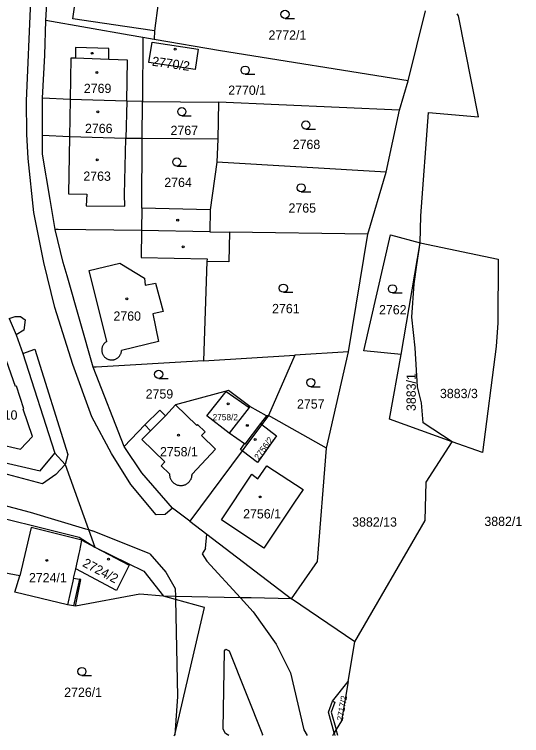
# Model space of a CAD drawing. Extents: x -527335 to -526256, y -1079142 to -1077809.
# Drawn here: x -526999.4 to -526906.2, y -1079141.5 to -1079009.2 of the extents above; entities that cross this region are included whole.
import ezdxf

# ---------------------------------------------------------------- set-up
doc = ezdxf.new("R2010")
doc.units = 0
for name, color, linetype in [('Vrstva 1', 7, 'Continuous'), ('Vrstva 2', 7, 'Continuous'), ('Vrstva 3', 7, 'Continuous'), ('Vrstva 4', 7, 'Continuous'), ('Vrstva 5', 7, 'Continuous')]:
    doc.layers.add(name, color=color, linetype=linetype)

msp = doc.modelspace()

# ---------------------------------------------------------------- linework, layer by layer
at = {"layer": 'Vrstva 1'}
for p, q in [((-526993.58, -1079010.29), (-526992.59, -1078994.21)), ((-526926.99, -1079021.34), (-526923.82, -1079008.49)), ((-526975.76, -1079013.38), (-526975.83, -1079025.14)), ((-526973.68, -1079013.74), (-526975.76, -1079013.38)), ((-526961.48, -1079015.86), (-526973.68, -1079013.74)), ((-526926.99, -1079021.34), (-526961.48, -1079015.86)), ((-526928.59, -1079026.75), (-526926.99, -1079021.34)), ((-526994.18, -1079031.41), (-526994.21, -1079024.51)), ((-526975.87, -1079031.93), (-526975.83, -1079025.14)), ((-526975.83, -1079025.14), (-526961.85, -1079025.27)), ((-526961.85, -1079025.27), (-526961.95, -1079032.04)), ((-526928.59, -1079026.75), (-526961.85, -1079025.27)), ((-526931.03, -1079038.09), (-526928.59, -1079026.75)), ((-526961.95, -1079032.04), (-526975.87, -1079031.93)), ((-526961.95, -1079032.04), (-526962.14, -1079036.28)), ((-526962.14, -1079036.28), (-526963.38, -1079045.02)), ((-526931.03, -1079038.09), (-526962.14, -1079036.28)), ((-526934.42, -1079049.52), (-526931.03, -1079038.09)), ((-526963.38, -1079045.02), (-526963.42, -1079049.05)), ((-526963.42, -1079049.05), (-526959.83, -1079049.11)), ((-526934.42, -1079049.52), (-526959.83, -1079049.11)), ((-526937.98, -1079071.07), (-526934.42, -1079049.52)), ((-526928.28, -1079071.58), (-526924.77, -1079051.08)), ((-526964.58, -1079072.72), (-526947.84, -1079071.72)), ((-526947.84, -1079071.72), (-526952.64, -1079082.8)), ((-526937.98, -1079071.07), (-526947.84, -1079071.72)), ((-526942, -1079088.79), (-526937.98, -1079071.07)), ((-526979.19, -1079088.45), (-526984.86, -1079073.9)), ((-526953.05, -1079082.84), (-526956.09, -1079081.1)), ((-526952.64, -1079082.8), (-526953.87, -1079084.41)), ((-526952.64, -1079082.8), (-526953.05, -1079082.84)), ((-526942, -1079088.79), (-526952.64, -1079082.8)), ((-526957.52, -1079089.25), (-526967.13, -1079102.16)), ((-526943.64, -1079109.56), (-526942, -1079088.79)), ((-526948.41, -1079116.44), (-526943.64, -1079109.56)), ((-526936.82, -1079124.34), (-526948.41, -1079116.44)), ((-526938.05, -1079131.59), (-526936.82, -1079124.34))]:
    msp.add_line(p, q, dxfattribs=at)
for points in [[(-526972.18, -1078997.1), (-526972.98, -1079000.63), (-526972.95, -1079007.03), (-526973.6, -1079012.17), (-526973.68, -1079013.74)], [(-526924.77, -1079051.08), (-526924.66, -1079046.13), (-526923.27, -1079027.14), (-526914.08, -1079027.98), (-526917.74, -1079009.39), (-526917.97, -1079009.06)], [(-526994.21, -1079024.51), (-526993.76, -1079016.63), (-526993.58, -1079010.29)], [(-526975.76, -1079013.38), (-526978.26, -1079012.95), (-526993.58, -1079010.29)], [(-526974.63, -1079018), (-526974.06, -1079014.26), (-526965.59, -1079015.55), (-526966.15, -1079019.3), (-526974.63, -1079018)], [(-526975.83, -1079025.14), (-526978.72, -1079025.11), (-526989.12, -1079024.77), (-526994.21, -1079024.51)], [(-526991.83, -1079048.67), (-526992.77, -1079043.16), (-526994.21, -1079034.79), (-526994.18, -1079031.41)], [(-526975.87, -1079031.93), (-526978.87, -1079031.91), (-526989.23, -1079031.65), (-526994.18, -1079031.41)], [(-526963.38, -1079045.02), (-526975.94, -1079044.75), (-526975.87, -1079031.93)], [(-526963.42, -1079049.05), (-526976, -1079048.8), (-526991.33, -1079048.67), (-526991.83, -1079048.67)], [(-526984.86, -1079073.9), (-526989.68, -1079057.15), (-526990.38, -1079054.69), (-526991.83, -1079048.67)], [(-526959.83, -1079049.11), (-526959.97, -1079054.59), (-526963.97, -1079054.51), (-526964.58, -1079072.72)], [(-526928.28, -1079071.58), (-526935.16, -1079070.89), (-526930.27, -1079049.59), (-526924.77, -1079051.08)], [(-526918.92, -1079087.59), (-526924.25, -1079084.15), (-526924.53, -1079080.46), (-526925.29, -1079077.55), (-526925.71, -1079070.34), (-526926.3, -1079064.74), (-526925.9, -1079058.59), (-526925.39, -1079055.11), (-526924.77, -1079051.08)], [(-526924.77, -1079051.08), (-526910.45, -1079054.06), (-526910.54, -1079065.78), (-526910.82, -1079070.11), (-526913.35, -1079089.58), (-526918.92, -1079087.59)], [(-527000.3, -1079064.95), (-526999.03, -1079067.99), (-526997.79, -1079071.43), (-526991.96, -1079089.49), (-526991.9, -1079089.68)], [(-526918.92, -1079087.59), (-526930.42, -1079083.47), (-526928.28, -1079071.58)], [(-526964.58, -1079072.72), (-526984.32, -1079073.9), (-526984.86, -1079073.9)], [(-526956.09, -1079081.1), (-526960.02, -1079078.17), (-526969.73, -1079080.81), (-526971.59, -1079082.86), (-526972.64, -1079081.8), (-526975.39, -1079084.5), (-526979.19, -1079088.45)], [(-526953.05, -1079082.84), (-526954.11, -1079084.23), (-526957, -1079088.03), (-526957.07, -1079087.98), (-526959.89, -1079086.05), (-526963.98, -1079082.86), (-526960.43, -1079078.38), (-526956.23, -1079081.29), (-526956.09, -1079081.1)], [(-526953.87, -1079084.41), (-526956.71, -1079088.16), (-526957.52, -1079089.25)], [(-526953.87, -1079084.41), (-526951.17, -1079086.54), (-526954.69, -1079091.43), (-526957.52, -1079089.25)], [(-526936.82, -1079124.34), (-526923.9, -1079102.05), (-526923.68, -1079095.01), (-526918.92, -1079087.59)], [(-526967.13, -1079102.16), (-526970.32, -1079099.79), (-526975.94, -1079093.33), (-526979.19, -1079088.45)], [(-527006.59, -1079090.18), (-526994.63, -1079092.92), (-526991.9, -1079089.68)], [(-526991.9, -1079089.68), (-526990.02, -1079091.79), (-526985.75, -1079103.72), (-526984.58, -1079106.98)], [(-527008.36, -1079099.95), (-526996.25, -1079102.89), (-526987.44, -1079105.14), (-526984.58, -1079106.98)], [(-526967.13, -1079102.16), (-526963.98, -1079104.57), (-526948.41, -1079116.44)], [(-526984.58, -1079106.98), (-526978.28, -1079110.24), (-526980.57, -1079114.9), (-526988.08, -1079110.95), (-526987.42, -1079108.12), (-526987.3, -1079107.62), (-526986.99, -1079105.64), (-526984.58, -1079106.98)], [(-526984.58, -1079106.98), (-526975.58, -1079111.34), (-526971.93, -1079115.94)], [(-526971.93, -1079115.94), (-526976.33, -1079115.57), (-526988.12, -1079117.78), (-526988.51, -1079117.72), (-526989.62, -1079117.54), (-526999.27, -1079115.18), (-526998.37, -1079112.24), (-527009.82, -1079110.06)], [(-526969.89, -1079141.41), (-526964.4, -1079118), (-526969.76, -1079116.53), (-526971.93, -1079115.94)], [(-526948.41, -1079116.44), (-526955.84, -1079116.28), (-526957.82, -1079116.24), (-526969.77, -1079115.99), (-526971.93, -1079115.94)], [(-526940.61, -1079141.01), (-526941.63, -1079137.22), (-526940.92, -1079135.23), (-526938.05, -1079131.59)], [(-526938.05, -1079131.59), (-526939.27, -1079138.83), (-526940.25, -1079140.42), (-526940.61, -1079141.01)], [(-526940.86, -1079141.53), (-526940.61, -1079141.01)], [(-526970.05, -1079141.53), (-526969.89, -1079141.41)]]:
    msp.add_lwpolyline(points, dxfattribs=at)
at = {"layer": 'Vrstva 3'}
for p, q in [((-526949.62, -1079009.9), (-526947.87, -1079009.9)), ((-526956.95, -1079020.15), (-526955.2, -1079020.15)), ((-526968.59, -1079027.75), (-526966.84, -1079027.75)), ((-526945.8, -1079030.21), (-526944.05, -1079030.21)), ((-526969.5, -1079037), (-526967.75, -1079037)), ((-526946.65, -1079041.73), (-526944.9, -1079041.73)), ((-526949.92, -1079060.16), (-526948.17, -1079060.16)), ((-526929.87, -1079060.28), (-526928.12, -1079060.28)), ((-526972.83, -1079075.98), (-526971.08, -1079075.98)), ((-526944.89, -1079077.49), (-526943.14, -1079077.49)), ((-526986.95, -1079130.53), (-526985.2, -1079130.53))]:
    msp.add_line(p, q, dxfattribs=at)
for centre in [(-526949.62, -1079009.15), (-526956.95, -1079019.4), (-526968.59, -1079027), (-526945.8, -1079029.46), (-526969.5, -1079036.25), (-526946.65, -1079040.98), (-526949.92, -1079059.41), (-526929.87, -1079059.53), (-526972.83, -1079075.23), (-526944.89, -1079076.74), (-526986.95, -1079129.78)]:
    msp.add_circle(centre, 0.75, dxfattribs=at)
at = {"layer": 'Vrstva 4'}
for p, q in [((-526988.63, -1079009.95), (-526987.21, -1078999.98)), ((-526997.1, -1079025), (-526996.31, -1079006.69)), ((-526979.03, -1079011.37), (-526988.63, -1079009.95)), ((-526973.6, -1079012.17), (-526979.03, -1079011.37)), ((-526988.11, -1079015.21), (-526988.12, -1079017.21)), ((-526982.01, -1079015.44), (-526988.11, -1079015.21)), ((-526982.02, -1079017.44), (-526982.01, -1079015.44)), ((-526988.99, -1079017.18), (-526989.12, -1079024.77)), ((-526988.12, -1079017.21), (-526988.99, -1079017.18)), ((-526982.02, -1079017.44), (-526988.12, -1079017.21)), ((-526978.56, -1079017.57), (-526982.02, -1079017.44)), ((-526978.72, -1079025.11), (-526978.56, -1079017.57)), ((-526997.09, -1079031.14), (-526997.1, -1079025)), ((-526989.12, -1079024.77), (-526989.23, -1079031.65)), ((-526978.72, -1079025.11), (-526978.87, -1079031.91)), ((-526996.85, -1079035.58), (-526997.09, -1079031.14)), ((-526989.23, -1079031.65), (-526989.41, -1079042.08)), ((-526979.09, -1079042.22), (-526978.87, -1079031.91)), ((-526995.75, -1079045.53), (-526996.85, -1079035.58)), ((-526989.41, -1079042.08), (-526986.04, -1079042.13)), ((-526986.04, -1079042.13), (-526986.18, -1079044.27)), ((-526979.05, -1079044.35), (-526979.09, -1079042.22)), ((-526986.18, -1079044.27), (-526979.05, -1079044.35)), ((-526993.94, -1079054.67), (-526995.75, -1079045.53)), ((-526975.94, -1079044.75), (-526976, -1079048.8)), ((-526976, -1079048.8), (-526976.07, -1079053.8)), ((-526991.93, -1079062.93), (-526993.94, -1079054.67)), ((-526985.61, -1079056.17), (-526979.98, -1079054.79)), ((-526979.98, -1079054.79), (-526975.45, -1079057.6)), ((-526976.07, -1079053.8), (-526963.96, -1079054.01)), ((-526963.96, -1079054.01), (-526963.97, -1079054.51)), ((-526982.38, -1079069.18), (-526985.61, -1079056.17)), ((-526975.45, -1079057.6), (-526975.34, -1079058.88)), ((-526975.34, -1079058.88), (-526973.41, -1079058.52)), ((-526973.41, -1079058.52), (-526972.01, -1079063.72)), ((-526988.62, -1079073.43), (-526991.93, -1079062.93)), ((-526972.01, -1079063.72), (-526973.93, -1079064.11)), ((-526973.93, -1079064.11), (-526972.86, -1079069.19)), ((-527000.3, -1079064.95), (-526999.18, -1079064.63)), ((-526999.18, -1079064.63), (-526998.24, -1079064.6)), ((-526998.24, -1079064.6), (-526997.4, -1079065.25)), ((-526997.4, -1079065.25), (-526997.64, -1079067.14)), ((-526997.64, -1079067.14), (-526999.03, -1079067.99)), ((-526972.86, -1079069.19), (-526979.66, -1079070.86)), ((-526997.79, -1079071.43), (-526995.59, -1079070.62)), ((-526995.59, -1079070.62), (-526989.55, -1079089.95)), ((-526999.16, -1079077.44), (-527000.78, -1079072.77)), ((-526985.11, -1079083.05), (-526988.62, -1079073.43)), ((-526998.99, -1079077.38), (-526999.16, -1079077.44)), ((-526997.6, -1079081.58), (-526998.99, -1079077.38)), ((-526965.85, -1079084.59), (-526969.73, -1079080.81)), ((-526956.23, -1079081.29), (-526959.89, -1079086.05)), ((-526997.76, -1079081.63), (-526997.6, -1079081.58)), ((-526996.01, -1079086.61), (-526997.76, -1079081.63)), ((-526981.48, -1079089.76), (-526985.11, -1079083.05)), ((-526971.59, -1079082.86), (-526974.33, -1079085.57)), ((-526974.33, -1079085.57), (-526975.39, -1079084.5)), ((-526965.7, -1079084.43), (-526965.85, -1079084.59)), ((-526964.32, -1079085.78), (-526965.7, -1079084.43)), ((-526954.11, -1079084.23), (-526953.87, -1079084.41)), ((-526998.21, -1079088.98), (-526996.01, -1079086.61)), ((-526974.33, -1079085.57), (-526975.94, -1079087.16)), ((-526964.95, -1079086.43), (-526964.32, -1079085.78)), ((-526962.37, -1079088.96), (-526964.95, -1079086.43)), ((-527005.52, -1079087.25), (-526998.21, -1079088.98)), ((-526975.94, -1079087.16), (-526971.7, -1079091.28)), ((-526957.8, -1079089.04), (-526957.07, -1079087.98)), ((-526966.71, -1079093.57), (-526962.37, -1079088.96)), ((-526957.52, -1079089.25), (-526957.8, -1079089.04)), ((-526989.55, -1079089.95), (-526990.02, -1079091.79)), ((-526977.96, -1079095.46), (-526981.48, -1079089.76)), ((-526994.16, -1079095.3), (-527010.79, -1079090.93)), ((-526990.02, -1079091.79), (-526991.73, -1079093.6)), ((-526971.7, -1079091.28), (-526972.4, -1079092)), ((-526972.4, -1079092), (-526970.84, -1079093.51)), ((-526954.61, -1079094.38), (-526952.95, -1079092.04)), ((-526952.95, -1079092.04), (-526946.32, -1079096.34)), ((-526991.73, -1079093.6), (-526994.16, -1079095.3)), ((-526961.27, -1079101.93), (-526955.72, -1079093.58)), ((-526955.72, -1079093.58), (-526954.61, -1079094.38)), ((-526973.28, -1079101.02), (-526977.96, -1079095.46)), ((-526946.32, -1079096.34), (-526947.9, -1079098.7)), ((-527007.27, -1079097.63), (-526996.46, -1079100.53)), ((-526970.32, -1079099.79), (-526971.63, -1079100.94)), ((-526947.9, -1079098.7), (-526953.53, -1079107.13)), ((-526996.46, -1079100.53), (-526986.26, -1079103.57)), ((-526971.63, -1079100.94), (-526973.28, -1079101.02)), ((-526953.53, -1079107.13), (-526961.27, -1079101.93)), ((-526996.25, -1079103.37), (-526998.37, -1079112.24)), ((-526986.99, -1079105.64), (-526996.25, -1079103.37)), ((-526986.26, -1079103.57), (-526985.75, -1079103.72)), ((-526985.75, -1079103.72), (-526984.99, -1079103.95)), ((-526974.48, -1079108.2), (-526984.99, -1079103.95)), ((-526964.26, -1079107.2), (-526963.98, -1079104.57)), ((-526964.26, -1079107.2), (-526964.86, -1079108.17)), ((-526974.48, -1079108.2), (-526971.51, -1079111.54)), ((-526964.86, -1079108.17), (-526964.02, -1079109.55)), ((-526964.02, -1079109.55), (-526957.82, -1079116.24)), ((-526988.47, -1079112.63), (-526988.08, -1079110.95)), ((-526971.51, -1079111.54), (-526969.8, -1079114.52)), ((-526988.47, -1079112.63), (-526989.62, -1079117.54)), ((-526987.41, -1079112.83), (-526988.51, -1079117.72)), ((-526988.47, -1079112.63), (-526987.41, -1079112.83)), ((-526988.12, -1079117.78), (-526987.13, -1079112.88)), ((-526987.13, -1079112.88), (-526987.41, -1079112.83)), ((-526969.8, -1079114.52), (-526969.77, -1079115.99)), ((-526969.77, -1079115.99), (-526969.76, -1079116.53)), ((-526969.76, -1079116.53), (-526969.39, -1079134.36)), ((-526957.82, -1079116.24), (-526955.45, -1079118.79)), ((-526955.45, -1079118.79), (-526951.28, -1079124.76)), ((-526951.28, -1079124.76), (-526948.63, -1079130.01)), ((-526960.96, -1079140.36), (-526960.76, -1079125.95)), ((-526960.76, -1079125.95), (-526960.52, -1079125.68)), ((-526960.52, -1079125.68), (-526959.9, -1079125.99)), ((-526959.9, -1079125.99), (-526953.77, -1079141.32)), ((-526948.63, -1079130.01), (-526946.15, -1079140.47)), ((-526969.39, -1079134.36), (-526969.89, -1079141.41)), ((-526940.46, -1079135.38), (-526941.14, -1079137.26)), ((-526940.92, -1079135.23), (-526940.46, -1079135.38)), ((-526941.14, -1079137.26), (-526940.25, -1079140.42)), ((-526960.57, -1079141.16), (-526960.96, -1079140.36)), ((-526946.15, -1079140.47), (-526945.56, -1079141.53)), ((-526940.61, -1079141.01), (-526940.46, -1079141.53)), ((-526939.93, -1079141.53), (-526940.25, -1079140.42)), ((-526969.89, -1079141.41), (-526969.95, -1079141.53)), ((-526959.92, -1079141.53), (-526960.57, -1079141.16)), ((-526953.77, -1079141.32), (-526953.81, -1079141.53))]:
    msp.add_line(p, q, dxfattribs=at)
for points in [[(-526982.38, -1079069.18), (-526982.48, -1079069.24), (-526982.58, -1079069.31), (-526982.67, -1079069.39), (-526982.76, -1079069.47), (-526982.84, -1079069.56), (-526982.92, -1079069.65), (-526982.99, -1079069.75), (-526983.06, -1079069.85), (-526983.11, -1079069.95), (-526983.16, -1079070.06), (-526983.2, -1079070.17), (-526983.24, -1079070.29), (-526983.27, -1079070.4), (-526983.29, -1079070.52), (-526983.3, -1079070.64), (-526983.3, -1079070.76), (-526983.3, -1079070.88), (-526983.29, -1079071), (-526983.27, -1079071.12), (-526983.24, -1079071.24), (-526983.21, -1079071.35), (-526983.17, -1079071.46), (-526983.12, -1079071.57), (-526983.06, -1079071.68), (-526983, -1079071.78), (-526982.93, -1079071.88), (-526982.85, -1079071.97), (-526982.77, -1079072.06), (-526982.68, -1079072.14), (-526982.59, -1079072.22), (-526982.49, -1079072.28), (-526982.39, -1079072.35), (-526982.28, -1079072.4), (-526982.17, -1079072.45), (-526982.06, -1079072.5), (-526981.95, -1079072.53), (-526981.83, -1079072.56), (-526981.71, -1079072.57), (-526981.59, -1079072.59), (-526981.47, -1079072.59), (-526981.35, -1079072.58), (-526981.23, -1079072.57), (-526981.11, -1079072.55), (-526981, -1079072.52), (-526980.88, -1079072.49), (-526980.77, -1079072.45), (-526980.66, -1079072.4), (-526980.56, -1079072.34), (-526980.45, -1079072.27), (-526980.36, -1079072.2), (-526980.27, -1079072.12), (-526980.18, -1079072.04), (-526980.1, -1079071.95), (-526980.02, -1079071.86), (-526979.95, -1079071.76), (-526979.89, -1079071.66), (-526979.84, -1079071.55), (-526979.79, -1079071.44), (-526979.75, -1079071.33), (-526979.71, -1079071.22), (-526979.69, -1079071.1), (-526979.67, -1079070.98), (-526979.66, -1079070.86)], [(-526970.84, -1079093.51), (-526970.84, -1079093.64), (-526970.83, -1079093.77), (-526970.82, -1079093.89), (-526970.79, -1079094.02), (-526970.76, -1079094.14), (-526970.72, -1079094.27), (-526970.67, -1079094.39), (-526970.62, -1079094.5), (-526970.56, -1079094.61), (-526970.49, -1079094.72), (-526970.41, -1079094.83), (-526970.33, -1079094.93), (-526970.24, -1079095.02), (-526970.15, -1079095.11), (-526970.05, -1079095.19), (-526969.95, -1079095.27), (-526969.84, -1079095.34), (-526969.73, -1079095.4), (-526969.61, -1079095.46), (-526969.5, -1079095.5), (-526969.37, -1079095.54), (-526969.25, -1079095.58), (-526969.12, -1079095.6), (-526969, -1079095.62), (-526968.87, -1079095.63), (-526968.74, -1079095.63), (-526968.61, -1079095.63), (-526968.49, -1079095.61), (-526968.36, -1079095.59), (-526968.23, -1079095.56), (-526968.11, -1079095.52), (-526967.99, -1079095.48), (-526967.87, -1079095.43), (-526967.76, -1079095.37), (-526967.65, -1079095.3), (-526967.55, -1079095.23), (-526967.45, -1079095.15), (-526967.35, -1079095.06), (-526967.26, -1079094.97), (-526967.18, -1079094.87), (-526967.1, -1079094.77), (-526967.03, -1079094.67), (-526966.96, -1079094.55), (-526966.9, -1079094.44), (-526966.85, -1079094.32), (-526966.81, -1079094.2), (-526966.77, -1079094.08), (-526966.75, -1079093.95), (-526966.73, -1079093.83), (-526966.71, -1079093.7), (-526966.71, -1079093.57)]]:
    msp.add_lwpolyline(points, dxfattribs=at)
at = {"layer": 'Vrstva 5'}
for centre in [(-526985.05, -1079016.3), (-526969.82, -1079015.54), (-526984.18, -1079019.84), (-526984, -1079027.06), (-526984.12, -1079035.85), (-526969.35, -1079046.94), (-526968.33, -1079051.81), (-526978.67, -1079061.37), (-526960.06, -1079080.65), (-526956.55, -1079084.59), (-526969.21, -1079086.41), (-526955.09, -1079087.19), (-526954.18, -1079097.74), (-526993.38, -1079109.37), (-526982.08, -1079109.15)]:
    msp.add_circle(centre, 0.175, dxfattribs=at)

# ---------------------------------------------------------------- texts
at = {"layer": 'Vrstva 2'}
for s, height, p in [('2772/1', 1.7, (-526952.66, -1079013.8)), ('2769', 1.7, (-526986.59, -1079023.59)), ('2770/1', 1.7, (-526960.06, -1079023.92)), ('2766', 1.7, (-526986.38, -1079030.93)), ('2767', 1.7, (-526970.66, -1079031.3)), ('2768', 1.7, (-526948.21, -1079033.87)), ('2763', 1.7, (-526986.68, -1079039.7)), ('2764', 1.7, (-526971.81, -1079040.85)), ('2765', 1.7, (-526948.98, -1079045.54)), ('2761', 1.7, (-526952, -1079064)), ('2762', 1.7, (-526932.35, -1079064.22)), ('2760', 1.7, (-526981.15, -1079065.38)), ('2759', 1.7, (-526975.23, -1079079.67)), ('3883/3', 1.7, (-526921.15, -1079079.59)), ('2757', 1.7, (-526947.42, -1079081.51)), ('2810', 1.7, (-527003.85, -1079083.53)), ('2758/2', 1.14, (-526962.93, -1079083.66)), ('2758/1', 1.7, (-526972.6, -1079090.28)), ('2756/1', 1.7, (-526957.32, -1079101.68)), ('3882/1', 1.7, (-526912.99, -1079103.06)), ('3882/13', 1.7, (-526937.28, -1079103.18)), ('2724/1', 1.7, (-526996.68, -1079113.4)), ('2726/1', 1.7, (-526990.2, -1079134.43))]:
    msp.add_text(s, height=height, dxfattribs=at).set_placement(p)
for s, height, rotation, p in [('2770/2', 1.7, 352, (-526974.14, -1079018.56)), ('3883/1', 1.7, 90, (-526925.6, -1079081.96)), ('2756/2', 1.14, 54, (-526954.46, -1079091.02)), ('2724/2', 1.7, 332, (-526986.98, -1079110.38)), ('2717/2', 1.14, 80, (-526939.01, -1079138.9))]:
    msp.add_text(s, height=height, rotation=rotation, dxfattribs=at).set_placement(p)

doc.saveas('drawing.dxf')
